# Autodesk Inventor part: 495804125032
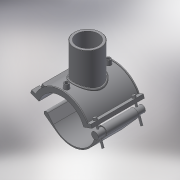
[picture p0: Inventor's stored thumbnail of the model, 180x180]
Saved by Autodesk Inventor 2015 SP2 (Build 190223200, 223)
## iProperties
Created: 2017-07
Part Number: 495804125032
Material: Generic
Description: PLASSON BRANCH SADDLE 125-32
Document SubType Name: Modeling
Designer: KIM
Density: 1 g/cm^3
Appearance: Default
Author: KIM
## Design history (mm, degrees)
derived "495804.ipt"
feature "Solid1::495804.ipt"
feature "Solid2::495804.ipt"
tag "TaggingFeature1"
body "Solid1"
body "Solid2"
other parameters: "d0" = 125, "d2" = 162, "d3" = 31.25, "d4" = 118, "d5" = 0, "d6" = 0.1, "d8" = 0, "d19" = 6, "d20" = 6, "d21" = 70.8, "d23" = 0, "d24" = 35.4, "d26" = 0, "d27" = 3, "d28" = 3, "d29" = 3, "d30" = 41.66667, "d31" = 6, "d32" = 0, "d33" = 0, "d34" = 0.6, "d40" = 75.4, "d41" = 35.2, "d43" = 0, "d45" = 0, "d47" = 131.5, "d48" = 32, "d50" = 0, "d70" = 15, "d72" = 0, "d73" = 6, "d75" = 5, "d76" = 0, "d77" = 6.25, "d78" = 92.5, "d79" = 15, "d80" = 47.2, "d82" = 5 deg, "d84" = 4, "d85" = 14, "d86" = 0, "d87" = 3, "d88" = 0, "d89" = 1, "d90" = 1, "d91" = 94.4, "d92" = 0, "d93" = 0.5, "d94" = 65.78947, "d96" = 147.9, "d97" = 2.36, "d98" = 0, "d102" = 0.96, "d103" = 25.6, "d105" = 0, "d109" = -19.66667, "d117" = 0.32, "d120" = 140 deg, "d121" = 24.228, "d122" = 20 deg, "d124" = 87, "d126" = 0, "d143" = 131.25, "d150" = 22.5, "d159" = 4, "d161" = 3.125, "d162" = 70.8, "d163" = 0, "d167" = 25, "d168" = 65.90909, "d173" = 1, "d175" = 62.5, "d176" = 20 deg, "d177" = 8.75, "d180" = 0, "d185" = 38.35, "d186" = 38.35, "d187" = 72.5, "d188" = 6, "d189" = 8.75, "d190" = 0, "d191" = 108.75, "d202" = 0, "d216" = 106.2, "d217" = 0, "d221" = 43.66, "d222" = 8.75, "d223" = 5.25, "d224" = 62.5, "d225" = 5.25, "d227" = 18, "d230" = 77.5, "d236" = 20 deg, "d237" = 79.5, "d238" = 20 deg, "d239" = 8.75, "d_" = 125, "B_" = 162, "H_" = 59, "L_" = 118, "d_t" = 6, "d_1" = 32, "H_1" = 49, "d1" = 145, "d148" = 3.125, "d160" = 3.125
